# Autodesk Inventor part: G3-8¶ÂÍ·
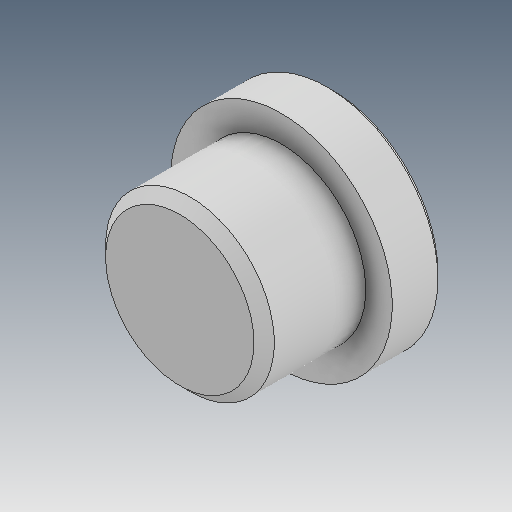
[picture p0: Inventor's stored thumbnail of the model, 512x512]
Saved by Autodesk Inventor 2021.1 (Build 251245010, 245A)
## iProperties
Created: 2019-12
Part Number: G3-8¶ÂÍ·
Material: Ogólny
Document SubType Name: Modeling
Designer: user
Density: 1 g/cm^3
Appearance: Domyślna
Author: user
Revision Number: ÈÎºÎ
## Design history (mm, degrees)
feature "ÊäÈë1"
node "Bryła1"
